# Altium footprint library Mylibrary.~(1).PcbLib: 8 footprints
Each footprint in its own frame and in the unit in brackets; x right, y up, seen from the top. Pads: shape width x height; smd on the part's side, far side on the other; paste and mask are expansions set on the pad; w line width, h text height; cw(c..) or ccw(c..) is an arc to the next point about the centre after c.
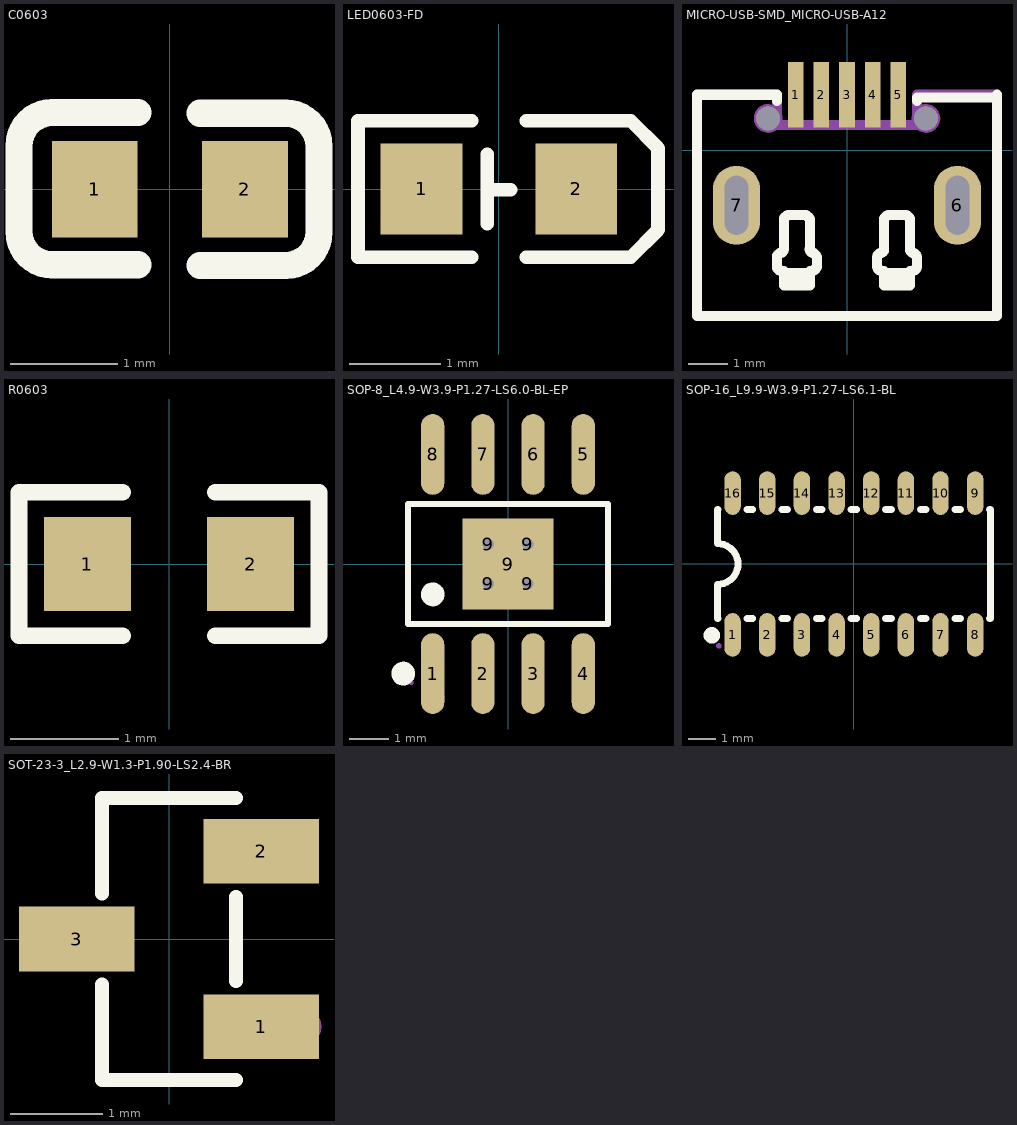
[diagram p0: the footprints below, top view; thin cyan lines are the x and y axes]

## C0603 [mm]
pads (2):
  rect 0.8x0.9 smd: 1(-0.7,0) 2(0.7,0)
Top Overlay:
  lines w0.254: -0.296,-0.704 -1.096,-0.704 cw(c-1.096,-0.394) -1.406,-0.394 -1.405,0.406 cw(c-1.096,0.406) -1.096,0.715 -0.296,0.715 ; 0.28,-0.71 1.08,-0.71 ccw(c1.08,-0.4) 1.39,-0.4 1.39,0.4 ccw(c1.08,0.4) 1.08,0.71 0.28,0.71

## LED0603-FD [mm]
pads (2):
  rect 0.9x1 smd: 1(-0.85,0) 2(0.85,0)
Top Overlay:
  lines w0.15: -1.55,-0.75 -0.3,-0.75 ; -1.55,-0.75 -1.55,0.73 ; -1.55,0.75 -0.3,0.75 ; -0.127,-0.381 -0.127,0.381 ; -0.127,-0.006 0.127,-0.006 ; 0.3,-0.75 1.45,-0.75 1.75,-0.45 1.75,-0.35 1.75,0.35 1.75,0.45 1.45,0.75 0.3,0.75
Mechanical 15:
  region: -1.1,0.1 -0.5,0.1 -0.5,-0.05 -1.1,-0.05
  region: 0.6,0.1 1.2,0.1 1.2,-0.05 0.6,-0.05
  region: -0.865,-0.273 -0.865,0.327 -0.715,0.327 -0.715,-0.273

## MICRO-USB-SMD_MICRO-USB-A12 [mm]
pads (9):
  rect 0.4x1.65 smd: 1(-1.3,1.4) 2(-0.65,1.4) 3(0,1.4) 4(0.65,1.4) 5(1.3,1.4)
  oval 1.2x2 hole 0.6 slot 1.5 at 90 deg: 6(2.799,-1.4) 7(-2.799,-1.4)
  round 0.6 hole 0.6 unplated: ""(-1.999,0.8) ""(1.999,0.8)
Top Overlay:
  lines w0.254: -1.778,-2.969 -1.778,-2.715 ; -1.778,1.241 -1.778,1.4 -3.8,1.4 -3.8,-4.2 3.8,-4.2 3.8,1.4 ; -1.775,-2.71 cw(c-1.675,-2.71) -1.675,-2.61 ; -1.773,-2.959 ccw(c-1.673,-2.959) -1.673,-3.059 ; -1.685,-2.609 ccw(c-1.698,-2.51) -1.598,-2.51 ; -1.676,-3.071 -1.6,-3.071 -1.6,-3.121 ; -1.6,-2.512 -1.6,-1.75 ; -1.598,-1.759 cw(c-1.498,-1.759) -1.498,-1.659 ; -1.499,-1.648 -1.041,-1.648 ; -1.048,-1.659 cw(c-1.048,-1.759) -0.948,-1.759 ; -0.948,-2.51 ccw(c-0.848,-2.51) -0.86,-2.609 ; -0.94,-2.512 -0.94,-1.75 ; -0.874,-2.61 cw(c-0.874,-2.71) -0.774,-2.71 ; -0.872,-3.058 ccw(c-0.872,-2.958) -0.772,-2.958 ; -0.864,-3.071 -0.94,-3.071 -0.94,-3.121 ; -0.762,-2.969 -0.762,-2.715 ; 0.762,-2.969 0.762,-2.715 ; 0.765,-2.71 cw(c0.865,-2.71) 0.865,-2.61 ; 0.767,-2.959 ccw(c0.867,-2.959) 0.867,-3.059 ; 0.855,-2.609 ccw(c0.842,-2.51) 0.942,-2.51 ; 0.864,-3.071 0.94,-3.071 0.94,-3.121 ; 0.94,-2.512 0.94,-1.75 ; 0.942,-1.759 cw(c1.042,-1.759) 1.042,-1.659 ; 1.041,-1.648 1.499,-1.648 ; 1.492,-1.659 cw(c1.492,-1.759) 1.592,-1.759 ; 1.592,-2.51 ccw(c1.692,-2.51) 1.68,-2.609 ; 1.6,-2.512 1.6,-1.75 ; 1.666,-2.61 cw(c1.666,-2.71) 1.766,-2.71 ; 1.668,-3.058 ccw(c1.668,-2.958) 1.768,-2.958 ; 1.676,-3.071 1.6,-3.071 1.6,-3.121 ; 1.778,-2.969 1.778,-2.715 ; 1.778,1.241 1.778,1.334 3.8,1.334 ; -1.6,-3.198 -0.94,-3.198 ; -1.6,-3.198 -1.6,-3.426 -0.94,-3.426 -0.94,-3.198 ; -1.6,-3.198 -1.6,-3.121 ; -1.6,-3.121 -0.94,-3.121 ; -0.94,-3.198 -0.94,-3.121 ; 0.94,-3.198 1.6,-3.198 ; 0.94,-3.198 0.94,-3.426 1.6,-3.426 1.6,-3.198 ; 0.94,-3.198 0.94,-3.121 ; 0.94,-3.121 1.6,-3.121 ; 1.6,-3.198 1.6,-3.121
Mechanical 4:
  circle w0.3: c1.999,0.8 r0.15
  circle w0.3: c-1.999,0.8 r0.15
Mechanical 5:
  circle w0.127: c1.999,0.8 r0.3
  circle w0.127: c-1.999,0.8 r0.3
Mechanical 15:
  lines w0.254: -3.8,1.4 -1.778,1.4 -1.778,0.638 1.778,0.638 1.778,1.4 3.8,1.4

## PCBComponent_1 [mm]

## R0603 [mm]
pads (2):
  rect 0.806x0.864 smd: 1(-0.753,0) 2(0.753,0)
Top Overlay:
  lines w0.152: -0.426,-0.661 -1.385,-0.661 -1.385,0.661 -0.426,0.661 ; 0.426,-0.661 1.385,-0.661 1.385,0.661 0.426,0.661
Top Paste:
  region: -0.355,0.4 -0.355,0.172 -0.735,0.172 -0.735,-0.158 -0.355,-0.158 -0.355,-0.4 -0.405,-0.45 -1.195,-0.45 -1.245,-0.4 -1.245,0.4 -1.195,0.45 -0.405,0.45
  region: 1.195,0.45 0.395,0.45 0.345,0.4 0.345,0.172 0.715,0.172 0.715,-0.158 0.345,-0.158 0.345,-0.4 0.395,-0.45 1.195,-0.45 1.245,-0.4 1.245,0.4

## SOP-8_L4.9-W3.9-P1.27-LS6.0-BL-EP [mm]
pads (13):
  oval 0.588x2.045 smd: 1(-1.905,-2.773) 2(-0.635,-2.773) 3(0.635,-2.773) 4(1.905,-2.773) 5(1.905,2.773) 6(0.635,2.773) 7(-0.635,2.773) 8(-1.905,2.773)
  round 0.6 hole 0.3: 9(-0.5,-0.5) 9(-0.5,0.5) 9(0.5,-0.5) 9(0.5,0.5)
  rect 2.29x2.29 smd: 9(0,0)
Top Overlay:
  circle w0.3: c-1.905,-0.769 r0.15
  circle w0.3: c-2.652,-2.772 r0.15
  lines w0.152: -2.526,-1.521 -2.526,1.521 2.526,1.521 2.526,-1.521 -2.526,-1.521
Mechanical 6:
  circle w0.06: c-2.45,-3 r0.03
Mechanical 15:
  circle w0.3: c-1.905,-3.4 r0.15

## SOP-16_L9.9-W3.9-P1.27-LS6.1-BL [mm]
pads (16):
  oval 0.6x1.6 smd: 1(-4.445,-2.6) 2(-3.175,-2.6) 3(-1.905,-2.6) 4(-0.635,-2.6) 5(0.635,-2.6) 6(1.905,-2.6) 7(3.175,-2.6) 8(4.445,-2.6) 9(4.445,2.6) 10(3.175,2.6) 11(1.905,2.6) 12(0.635,2.6) 13(-0.635,2.6) 14(-1.905,2.6) 15(-3.175,2.6) 16(-4.445,2.6)
Top Overlay:
  lines w0.254: -5,-0.751 ccw(c-5,-0.001) -5,0.75 -5,2 -4.976,2 ; -5,-0.75 -5,-2 -4.976,-2 ; -3.914,-2 -3.706,-2 ; -3.914,2 -3.706,2 ; -2.644,-2 -2.436,-2 ; -2.644,2 -2.436,2 ; -1.374,-2 -1.166,-2 ; -1.374,2 -1.166,2 ; -0.104,-2 0.104,-2 ; -0.104,2 0.104,2 ; 1.166,-2 1.374,-2 ; 1.166,2 1.374,2 ; 2.436,-2 2.644,-2 ; 2.436,2 2.644,2 ; 3.706,-2 3.914,-2 ; 3.706,2 3.914,2 ; 4.976,-2 5,-2 5,2 4.976,2
  lines w0.3: -5.207,-2.464 ccw(c-5.206,-2.614) -5.204,-2.464
Mechanical 5:
  pour cut-out: 4.663,2.22 4.663,1.94 4.227,1.94 4.227,2.22
  pour cut-out: 3.393,2.22 3.393,1.94 2.957,1.94 2.957,2.22
  pour cut-out: 2.123,2.22 2.123,1.94 1.687,1.94 1.687,2.22
  pour cut-out: 0.853,2.22 0.853,1.94 0.417,1.94 0.417,2.22
  pour cut-out: -0.417,2.22 -0.417,1.94 -0.853,1.94 -0.853,2.22
  pour cut-out: -1.687,2.22 -1.687,1.94 -2.123,1.94 -2.123,2.22
  pour cut-out: -2.957,2.22 -2.957,1.94 -3.393,1.94 -3.393,2.22
  pour cut-out: -4.227,2.22 -4.227,1.94 -4.663,1.94 -4.663,2.22
  pour cut-out: -4.663,-2.22 -4.663,-1.94 -4.227,-1.94 -4.227,-2.22
  pour cut-out: -3.393,-2.22 -3.393,-1.94 -2.957,-1.94 -2.957,-2.22
  pour cut-out: -2.123,-2.22 -2.123,-1.94 -1.687,-1.94 -1.687,-2.22
  pour cut-out: -0.853,-2.22 -0.853,-1.94 -0.417,-1.94 -0.417,-2.22
  pour cut-out: 0.417,-2.22 0.417,-1.94 0.853,-1.94 0.853,-2.22
  pour cut-out: 1.687,-2.22 1.687,-1.94 2.123,-1.94 2.123,-2.22
  pour cut-out: 2.957,-2.22 2.957,-1.94 3.393,-1.94 3.393,-2.22
  pour cut-out: 4.227,-2.22 4.227,-1.94 4.663,-1.94 4.663,-2.22
Mechanical 6:
  circle w0.1: c-4.95,-3 r0.05
Mechanical 15:
  circle w0.2: c-4.521,-2.82 r0.1

## SOT-23-3_L2.9-W1.3-P1.90-LS2.4-BR [mm]
pads (3):
  rect 1.25x0.7 smd: 1(1,-0.95) 2(1,0.95) 3(-1,0)
Top Overlay:
  lines w0.152: -0.726,-0.495 -0.726,-1.526 0.726,-1.526 ; -0.726,0.495 -0.726,1.526 0.726,1.526 ; 0.726,-0.455 0.726,0.455
Mechanical 15:
  circle w0.2: c1.45,-0.95 r0.1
